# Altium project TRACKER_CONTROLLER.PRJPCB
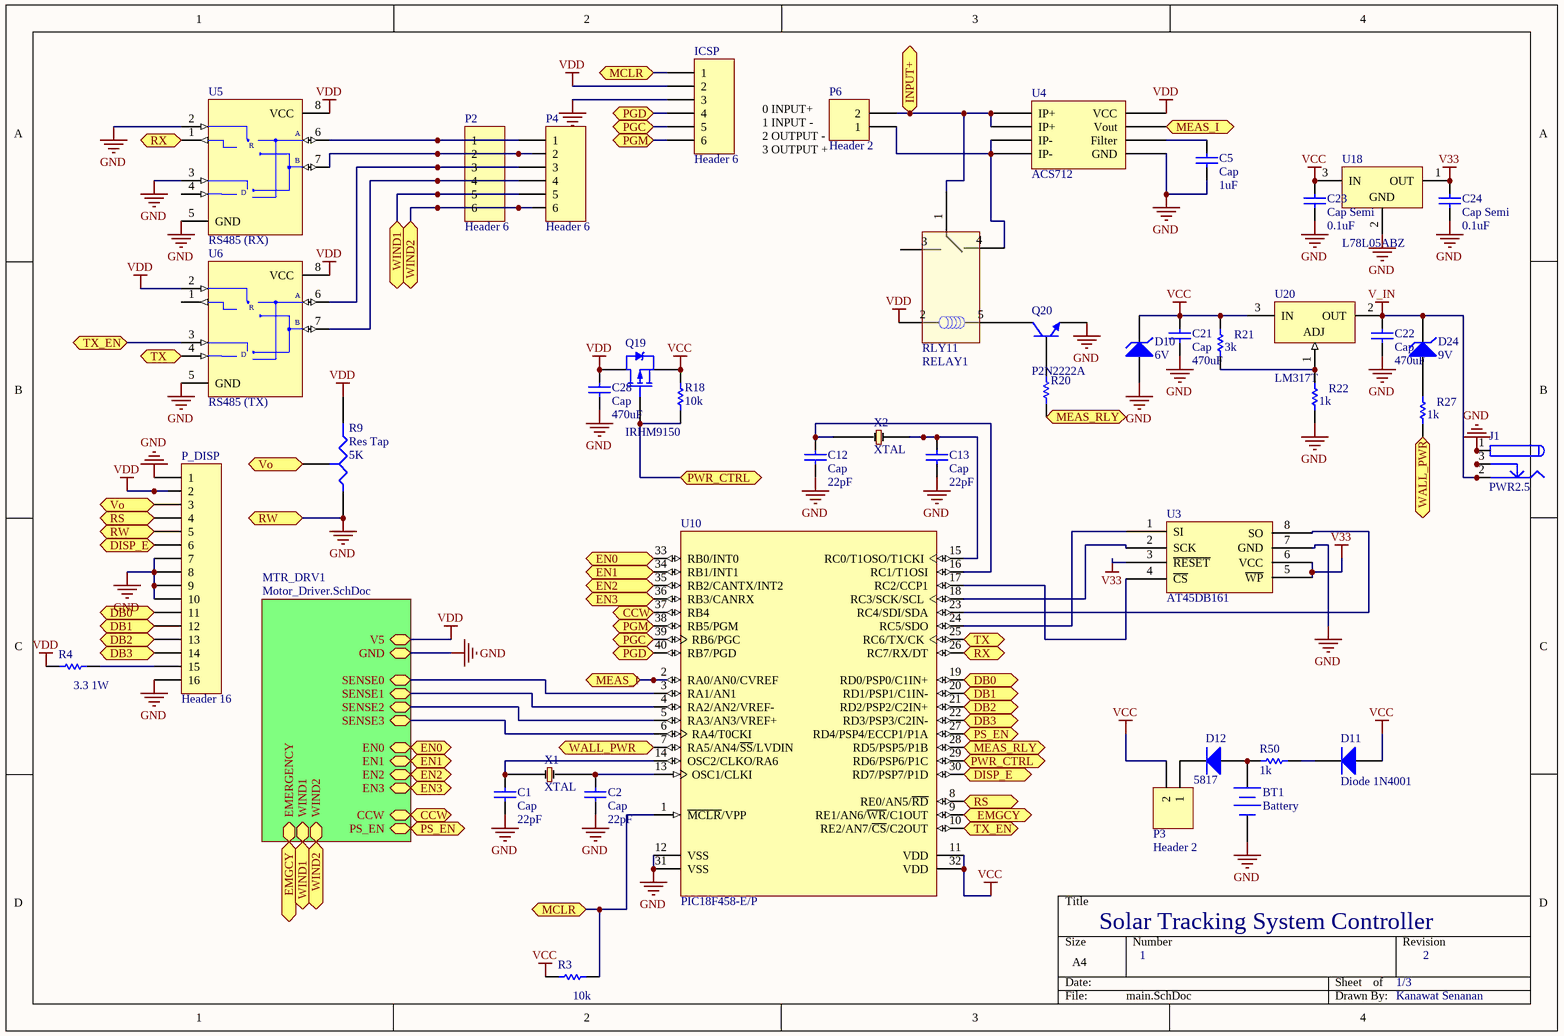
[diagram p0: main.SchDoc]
6 sheets, 202 parts. Net scope: hierarchical (ports join the sheet entries above them; power ports are global).
Board file: main_board.PcbDoc
Sheets:
  main.SchDoc
    MTR_DRV1 = Motor_Driver.SchDoc
      Sensor frontend = sensor_front.SchDoc
  Comm_interface.SchDoc
  current_logger.SchDoc
  main2.SchDoc
    MTR_DRV1 = Motor_Driver.SchDoc
      Sensor frontend = sensor_front.SchDoc

## Sheet main.SchDoc
size A4; PageSetup: Record=PageOptions|CenterHorizontal=True|CenterVertical=True|PrintScale=0.97|XCorrection=1.00|YCorrection=1.00|PrintKind=0|BorderSize=5000000|LeftOffset=0|BottomOffset=0|Orientation=2|PaperLength=1000|PaperWidth=1000|Scale=100|PaperSource=7|PrintQuality=-4|MediaType=1|DitherType=10|PaperKind=A4|PrintScaleMode=1

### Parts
(Parts that share a designator on the sheet are numbered #1, #2 ... from top to bottom, then left to right.)
BT1#1  Battery  [batt]
C1#1  Cap  value 22pF  [VP32-3.2]
C2#1  Cap  value 22pF  [VP32-3.2]
C5#1  Cap  value 1uF  [VP32-3.2]
C12#1  Cap  value 22pF  [VP32-3.2]
C13#1  Cap  value 22pF  [VP32-3.2]
C21#1  Cap  value 470uF  [Capacitor470u25v]
C22  Cap  value 470uF  [Capacitor470u25v]
C23#1  Cap Semi  value 0.1uF  [C1206]
C24#1  Cap Semi  value 0.1uF  [C1206]
C28#1  Cap  value 470uF  [Capacitor470u25v]
D10#1  6V  [DIODE-0.4]
D11#1  Diode 1N4001  [DO-41]
D12#1  5817  [DO-41]
D24  9V  [DIODE-0.4]
ICSP#1  Header 6  [HDR1X6]
J1  PWR2.5  [KLD-0202]
P2#1  Header 6  [PHONE_6]
P3#1  Header 2  [HDR1X2]
P4#1  Header 6  [PHONE_6]
P6#1  Header 2  [BLOCK_X2_762mm]
P_DISP#1  Header 16  [HDR1X16]
Q19#1  IRHM9150  [SSOT-3 - duplicate]
Q20  P2N2222A  [29-04]
R3#1  value 10k  [AXIAL-0.4]  (hidden comment: Res1)
R4#1  value 3.3 1W  [AXIAL-0.7]  (hidden comment: Res1)
R9#1  Res Tap  value 5K  [RPOT]
R18#1  value 10k  [AXIAL-0.4]  (hidden comment: Res1)
R20  Res1  [AXIAL-0.4]  (value not drawn)
R21  value 3k  [AXIAL-0.4]  (hidden comment: Res1)
R22  value 1k  [AXIAL-0.4]  (hidden comment: Res1)
R27  value 1k  [AXIAL-0.4]  (hidden comment: Res1)
R50#1  value 1k  [AXIAL-0.4]  (hidden comment: Res1)
RLY11  RELAY1  [SPDT]
U3#1  AT45DB161  [SOP8]
U4#1  ACS712  [751-05_N]
U5#1  RS485 (RX)  [PA8]
U6#1  RS485 (TX)  [PA8]
U10  PIC18F458-E/P  [PDIP600-40]
U18#1  L78L05ABZ  [TO92]
U20  LM317T  [221A-06]
X1#1  XTAL  [XTAL]
X2#1  XTAL  [XTAL]

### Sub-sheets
MTR_DRV1 = Motor_Driver.SchDoc: GND, SENSE0, SENSE1, SENSE2, SENSE3, EN0, EN1, EN2, EN3, CCW, V5, PS_EN, EMERGENCY, WIND1, WIND2

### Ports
CCW, DB0, DB1, DB2, DB3, DISP_E, EMGCY, EN0, EN1, EN2, EN3, INPUT+, MCLR, MEAS_I, MEAS_RLY, PGC, PGD, PGM, PS_EN, PWR_CTRL, RS, RW, RX, TX, TX_EN, Vo, WALL_PWR, WIND1, WIND2

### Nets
GND: BT1#1.2(-) C1#1.1 C2#1.1 C5#1.1 C12#1.1 C13#1.1 C21#1.2 C22.2 C23#1.1 C24#1.1 C28#1.2 D10#1.1(A) ICSP#1.3 J1.1 J1.1A J1.1B P_DISP#1.1 P_DISP#1.5 P_DISP#1.7 P_DISP#1.8 P_DISP#1.9 P_DISP#1.10 P_DISP#1.16 Q20.3(E) R9#1.1(A) R22.2 U3#1.7(GND) U4#1.5(GND) U5#1.2(~{RE}) U5#1.3(DE) U5#1.5(GND) U6#1.5(GND) U10.12(VSS) U10.31(VSS) U18#1.2(GND) ; port RW, sheet MTR_DRV1/GND
V33: C24#1.2 U3#1.3(~{RESET}) U3#1.5(~{WP}) U3#1.6(VCC) U18#1.1(OUT)
V_IN: C22.1 D24.2(K) J1.2 J1.2A J1.2B U20.2(OUT)
VCC: C21#1.1 C23#1.2 D10#1.2(K) D11#1.1(A) P3#1.2 Q19#1.2(S) R3#1.2 R18#1.1 R21.1 U10.11(VDD) U10.32(VDD) U18#1.3(IN) U20.3(IN)
VDD: C28#1.1 ICSP#1.2 P_DISP#1.2 Q19#1.1(D) R4#1.2 R9#1.2(B) RLY11.2 U4#1.8(VCC) U5#1.8(VCC) U6#1.2(~{RE}) U6#1.8(VCC) ; sheet MTR_DRV1/V5  [project net V5]
NetBT1#1_1: BT1#1.1(+) D12#1.1(A) R50#1.1
NetC1#1_2: C1#1.2 U10.14(OSC2/CLKO/RA6) X1#1.1
NetC2#1_2: C2#1.2 U10.13(OSC1/CLKI) X1#1.0
NetC5#1_2: C5#1.2 U4#1.6(Filter)
NetC12#1_2: C12#1.2 U10.16(RC1/T1OSI) X2#1.0
NetC13#1_2: C13#1.2 U10.15(RC0/T1OSO/T1CKI) X2#1.1
NetD1_1: P2#1.6 P4#1.6 ; port WIND2, sheet MTR_DRV1/WIND2
NetD1_2: P2#1.5 P4#1.5 ; port WIND1, sheet MTR_DRV1/WIND1
NetD11#1_2: D11#1.2(K) R50#1.2
NetD12#1_2: D12#1.2(K) P3#1.1
NetD24_1: D24.1(A) R27.1
NetICSP#1_1: ICSP#1.1 R3#1.1 U10.1(~{MCLR}/VPP) ; port MCLR
NetICSP#1_4: ICSP#1.4 U10.40(RB7/PGD) ; port PGD
NetICSP#1_5: ICSP#1.5 U10.39(RB6/PGC) ; port PGC
NetICSP#1_6: ICSP#1.6 U10.38(RB5/PGM) ; port PGM
NetJ1_3: J1.3 J1.3A J1.3B
NetP2#1_1: P2#1.1 P4#1.1 U5#1.6(A)
NetP2#1_2: P2#1.2 P4#1.2 U5#1.7(B)
NetP2#1_3: P2#1.3 P4#1.3 U6#1.6(A)
NetP2#1_4: P2#1.4 P4#1.4 U6#1.7(B)
NetP6#1_1: P6#1.1 RLY11.4 U4#1.3(IP-) U4#1.4(IP-)
NetP6#1_2: P6#1.2 RLY11.1 U4#1.1(IP+) U4#1.2(IP+) ; port INPUT+
NetP_DISP#1_3: P_DISP#1.3 R9#1.3(TAP) ; port Vo
NetP_DISP#1_4: P_DISP#1.4 U10.8(RE0/AN5/~{RD}) ; port RS
NetP_DISP#1_6: P_DISP#1.6 U10.30(RD7/PSP7/P1D) ; port DISP_E
NetP_DISP#1_11: P_DISP#1.11 U10.19(RD0/PSP0/C1IN+) ; port DB0
NetP_DISP#1_12: P_DISP#1.12 U10.20(RD1/PSP1/C1IN-) ; port DB1
NetP_DISP#1_13: P_DISP#1.13 U10.21(RD2/PSP2/C2IN+) ; port DB2
NetP_DISP#1_14: P_DISP#1.14 U10.22(RD3/PSP3/C2IN-) ; port DB3
NetP_DISP#1_15: P_DISP#1.15 R4#1.1
NetQ19#1_3: Q19#1.3(G) R18#1.2 U10.29(RD6/PSP6/P1C) ; port PWR_CTRL
NetQ20_1: Q20.1(C) RLY11.5
NetQ20_2: Q20.2(B) R20.1
NetR2_2: U10.9(RE1/AN6/~{WR}/C1OUT) ; port EMGCY, sheet MTR_DRV1/EMERGENCY
NetR20_2: R20.2 U10.28(RD5/PSP5/P1B) ; port MEAS_RLY
NetR21_2: R21.2 R22.1 U20.1(ADJ)
NetR27_2: R27.2 U10.7(RA5/AN4/~{SS}/LVDIN) ; port WALL_PWR
NetR103_2: U10.37(RB4) ; port CCW, sheet MTR_DRV1/CCW
NetU3#1_1: U3#1.1(SI) U10.24(RC5/SDO)
NetU3#1_2: U3#1.2(SCK) U10.18(RC3/SCK/SCL)
NetU3#1_4: U3#1.4(~{CS}) U10.17(RC2/CCP1)
NetU3#1_8: U3#1.8(SO) U10.23(RC4/SDI/SDA)
NetU4#1_7: U4#1.7(Vout) U10.2(RA0/AN0/CVREF) ; port MEAS_I
NetU5#1_1: U5#1.1(RO) U10.26(RC7/RX/DT) ; port RX
NetU6#1_3: U6#1.3(DE) U10.10(RE2/AN7/~{CS}/C2OUT) ; port TX_EN
NetU6#1_4: U6#1.4(DI) U10.25(RC6/TX/CK) ; port TX
NetU7_1: U10.33(RB0/INT0) ; port EN0, sheet MTR_DRV1/EN0
NetU7_3: U10.34(RB1/INT1) ; port EN1, sheet MTR_DRV1/EN1
NetU7_5: U10.35(RB2/CANTX/INT2) ; port EN2, sheet MTR_DRV1/EN2
NetU7_7: U10.36(RB3/CANRX) ; port EN3, sheet MTR_DRV1/EN3
NetU8_2: U10.3(RA1/AN1) ; sheet MTR_DRV1/SENSE0
NetU8_4: U10.4(RA2/AN2/VREF-) ; sheet MTR_DRV1/SENSE1
NetU8_6: U10.5(RA3/AN3/VREF+) ; sheet MTR_DRV1/SENSE2
NetU8_8: U10.6(RA4/T0CKI) ; sheet MTR_DRV1/SENSE3
NetU10_27: U10.27(RD4/PSP4/ECCP1/P1A) ; port PS_EN, sheet MTR_DRV1/PS_EN

Not connected (* = marked no-connect by the designer): RLY11 3; U5#1 4(DI); U6#1 1(RO)

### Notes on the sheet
- (near P6#1) 0 INPUT+
  1 INPUT -
  2 OUTPUT -
  3 OUTPUT +
- Solar Tracking System Controller
- 1
- 1/3
- 2
- Kanawat Senanan

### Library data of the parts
BT1#1 = Battery: Multicell Battery
C1#1 C2#1 C5#1 C12#1 C13#1 C21#1 C22 C28#1 = Cap: Capacitor
C23#1 C24#1 = Cap Semi: Capacitor (Semiconductor SIM Model)
D10#1 D24 = D Zener: Zener Diode
D11#1 D12#1 = Diode 1N4001: 1 Amp General Purpose Rectifier
ICSP#1 P2#1 P4#1 = Header 6: Header, 6-Pin
J1 = PWR2.5: Low Voltage Power Supply Connector
P3#1 P6#1 = Header 2: Header, 2-Pin
P_DISP#1 = Header 16: Header, 16-Pin
Q19#1 = IRHM9150: Radiation Hardened HEXFET Power MOSFET
Q20 = P2N2222A: Amplifier Transistor NPN Silicon
R3#1 R4#1 R18#1 R21 R22 R27 R50#1 = Res1: Resistor
R9#1 = Res Tap: Tapped Resistor; pin to pad: 2>3 3>2; Sim Note: Enter the Resistance value and the set point into parameter fields.; Set Position: 0.5
R20 = Res1: Resistor; Value: 2k
U5#1 U6#1 = MAX485EPA: Low-Power, Slew-Rate-Limited RS-485/RS-422 Transceiver
U10 = PIC18F458-E/P: High Performance, Enhanced FLASH Microcontroller with CAN, 32K FLASH, 40-Pin PDIP, Standard Volt Range, Extended Temperature
U18#1 = L78L05ABZ: Positive Voltage Regulator
U20 = LM317T: Three-Terminal Adjustable Output Positive Voltage Regulator; Note: Heatsink surface connected to Pin 2

## Sheet Motor_Driver.SchDoc
size A4; PageSetup: Record=PageOptions|CenterHorizontal=True|CenterVertical=True|PrintScale=0.97|XCorrection=1.00|YCorrection=1.00|PrintKind=0|BorderSize=5000000|LeftOffset=0|BottomOffset=0|Orientation=2|PaperLength=1000|PaperWidth=1000|Scale=100|PaperSource=7|PrintQuality=-4|MediaType=1|DitherType=10|PaperKind=A4|PrintScaleMode=1
Used 2 times, as channels MTR_DRV1, MTR_DRV1. Parts and nets are listed once, with the designators drawn on the sheet.
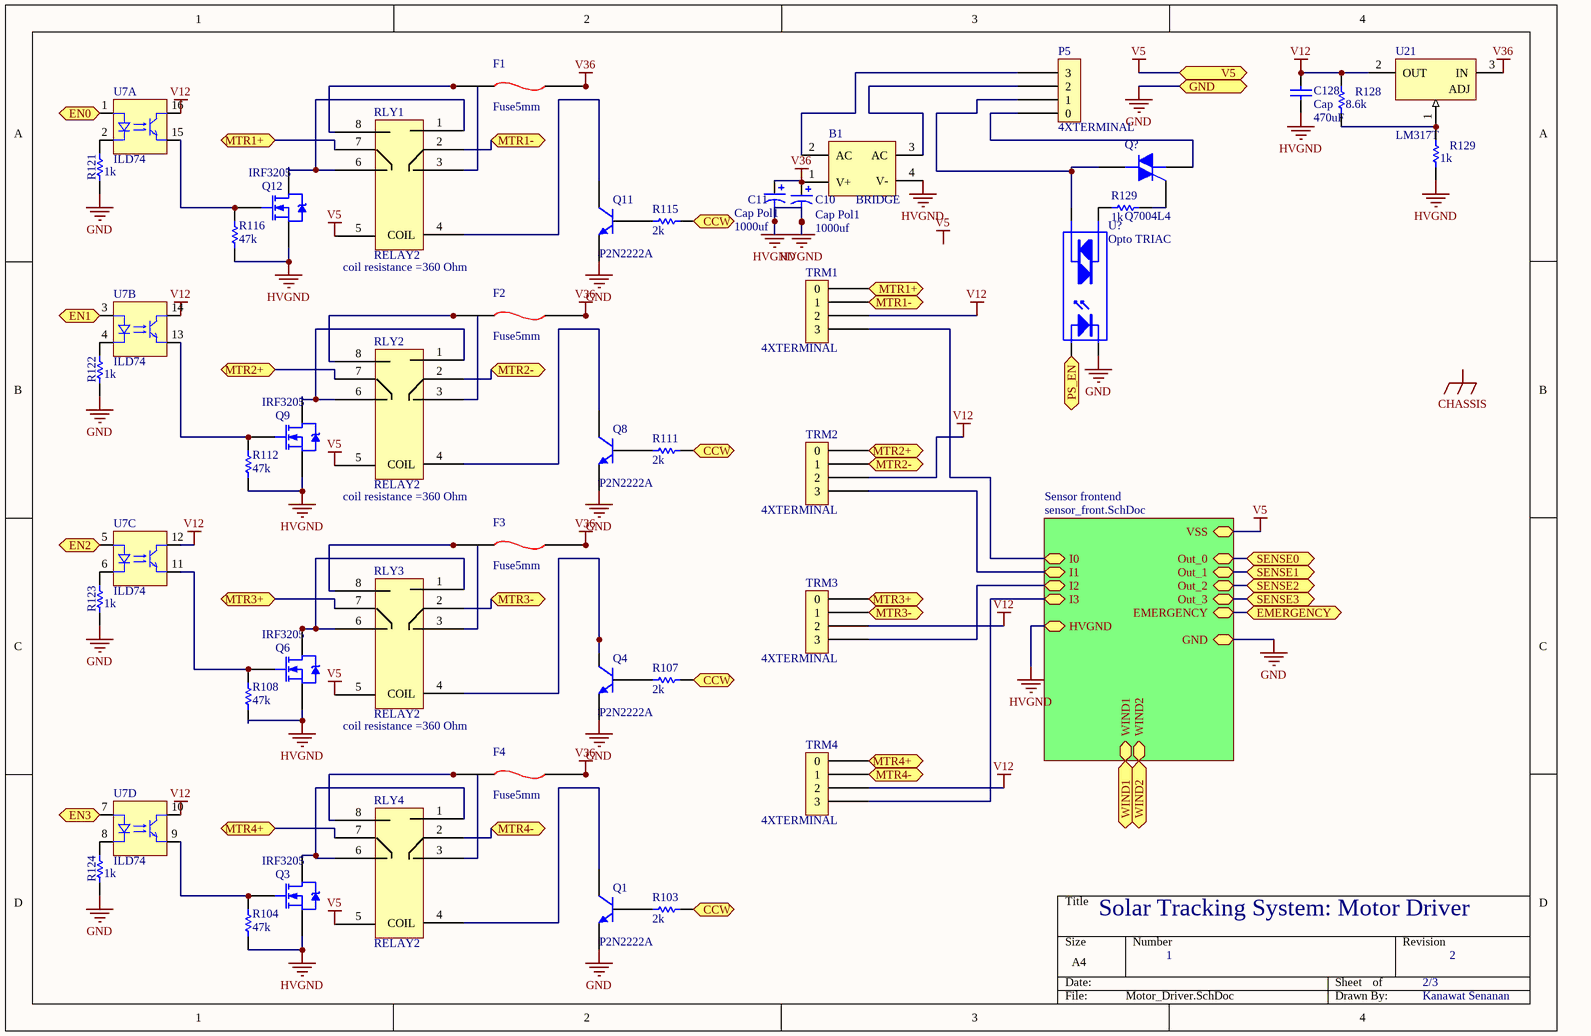
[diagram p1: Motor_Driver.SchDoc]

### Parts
(Parts that share a designator on the sheet are numbered #1, #2 ... from top to bottom, then left to right.)
B1  BRIDGE  [BRIDGE]
C10  Cap Pol1  value 1000uf  [Capacitor2200u50v]
C11  Cap Pol1  value 1000uf  [Capacitor2200u50v]
C128  Cap  value 470uF  [Capacitor470u25v]
F1  Fuse5mm  [Fuse5mm]
F2  Fuse5mm  [Fuse5mm]
F3  Fuse5mm  [Fuse5mm]
F4  Fuse5mm  [Fuse5mm]
P5  4XTERMINAL  [BLK_TERMX4]
Q1  P2N2222A  [29-04]
Q3  IRF3205  [TO-220AB]
Q4  P2N2222A  [29-04]
Q6  IRF3205  [TO-220AB]
Q8  P2N2222A  [29-04]
Q9  IRF3205  [TO-220AB]
Q11  P2N2222A  [29-04]
Q12  IRF3205  [TO-220AB]
Q?  Q7004L4  [TO-220AB]
R103  value 2k  [AXIAL-0.4]  (hidden comment: Res1)
R104  value 47k  [AXIAL-0.4]  (hidden comment: Res1)
R107  value 2k  [AXIAL-0.4]  (hidden comment: Res1)
R108  value 47k  [AXIAL-0.4]  (hidden comment: Res1)
R111  value 2k  [AXIAL-0.4]  (hidden comment: Res1)
R112  value 47k  [AXIAL-0.4]  (hidden comment: Res1)
R115  value 2k  [AXIAL-0.4]  (hidden comment: Res1)
R116  value 47k  [AXIAL-0.4]  (hidden comment: Res1)
R121  value 1k  [AXIAL-0.4]  (hidden comment: Res1)
R122  value 1k  [AXIAL-0.4]  (hidden comment: Res1)
R123  value 1k  [AXIAL-0.4]  (hidden comment: Res1)
R124  value 1k  [AXIAL-0.4]  (hidden comment: Res1)
R128  value 8.6k  [AXIAL-0.4]  (hidden comment: Res1)
R129#1  value 1k  [AXIAL-0.4]  (hidden comment: Res1)
R129#2  value 1k  [AXIAL-0.4]  (hidden comment: Res1)
RLY1  RELAY2  [DPDT_Relay]
RLY2  RELAY2  [DPDT_Relay]
RLY3  RELAY2  [DPDT_Relay]
RLY4  RELAY2  [DPDT_Relay]
TRM1  4XTERMINAL  [BLK_TERMX4]
TRM2  4XTERMINAL  [BLK_TERMX4]
TRM3  4XTERMINAL  [BLK_TERMX4]
TRM4  4XTERMINAL  [BLK_TERMX4]
U7  ILD74  [J016D]  (parts A,B,C,D of 4)
U21  LM317T  [221A-06]
U?  Opto TRIAC  [SIP-P4/A7.5]

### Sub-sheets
Sensor frontend = sensor_front.SchDoc: I0, I1, I2, I3, Out_0, Out_1, Out_2, Out_3, VSS, GND, HVGND, EMERGENCY, WIND1, WIND2

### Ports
CCW, EMERGENCY, EN0, EN1, EN2, EN3, GND, MTR1+, MTR1-, MTR2+, MTR2-, MTR3+, MTR3-, MTR4+, MTR4-, PS_EN, SENSE0, SENSE1, SENSE2, SENSE3, V5, WIND1, WIND2

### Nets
GND: Q1.3(E) Q4.3(E) Q8.3(E) Q11.3(E) R121.1 R122.1 R123.1 R124.1 U?.2(K) ; port GND, sheet Sensor frontend/GND
HVGND: B1.4(V-) C10.2 C11.2 C128.2 Q3.3(S) Q6.3(S) Q9.3(S) Q12.3(S) R104.1 R108.1 R112.1 R116.1 R129#1.2 ; sheet Sensor frontend/HVGND
V5: RLY1.5 RLY2.5 RLY3.5 RLY4.5 ; port V5, sheet Sensor frontend/VSS
V12: C128.1 R128.1 TRM1.2 TRM2.2 TRM3.2 TRM4.2 U7.10(C) U7.12(C) U7.14(C) U7.16(C) U21.2(OUT)
V36: B1.1(V+) C10.1 C11.1 F1.3 F1.4 F2.3 F2.4 F3.3 F3.4 F4.3 F4.4 U21.3(IN)
CCW: R103.2 R107.2 R111.2 R115.2 ; port CCW
EMERGENCY: port EMERGENCY, sheet Sensor frontend/EMERGENCY
EN0: U7.1(A) ; port EN0
EN1: U7.3(A) ; port EN1
EN2: U7.5(A) ; port EN2
EN3: U7.7(A) ; port EN3
MTR1+: RLY1.7 TRM1.0 ; port MTR1+
MTR1-: RLY1.2 TRM1.1 ; port MTR1-
MTR2+: RLY2.7 TRM2.0 ; port MTR2+
MTR2-: RLY2.2 TRM2.1 ; port MTR2-
MTR3+: RLY3.7 TRM3.0 ; port MTR3+
MTR3-: RLY3.2 TRM3.1 ; port MTR3-
MTR4+: RLY4.7 TRM4.0 ; port MTR4+
MTR4-: RLY4.2 TRM4.1 ; port MTR4-
PS_EN: U?.1(A) ; port PS_EN
SENSE0: port SENSE0, sheet Sensor frontend/Out_0
SENSE1: port SENSE1, sheet Sensor frontend/Out_1
SENSE2: port SENSE2, sheet Sensor frontend/Out_2
SENSE3: port SENSE3, sheet Sensor frontend/Out_3
WIND1: port WIND1, sheet Sensor frontend/WIND1
WIND2: port WIND2, sheet Sensor frontend/WIND2
NetB1_2: B1.2(AC) P5.3
NetB1_3: B1.3(AC) P5.2
NetF1_1: F1.1 F1.2 RLY1.3 RLY1.8
NetF2_1: F2.1 F2.2 RLY2.3 RLY2.8
NetF3_1: F3.1 F3.2 RLY3.3 RLY3.8
NetF4_1: F4.1 F4.2 RLY4.3 RLY4.8
NetP5_0: P5.0 Q?.1(M1)
NetP5_1: P5.1 Q?.2(M2) U?.3(A/K)
NetQ1_1: Q1.1(C) RLY4.4(COIL)
NetQ1_2: Q1.2(B) R103.1
NetQ3_1: Q3.1(G) R104.2 U7.9(E)
NetQ3_2: Q3.2(D) RLY4.1(NO) RLY4.6
NetQ4_1: Q4.1(C) RLY3.4(COIL)
NetQ4_2: Q4.2(B) R107.1
NetQ6_1: Q6.1(G) R108.2 U7.11(E)
NetQ6_2: Q6.2(D) RLY3.1(NO) RLY3.6
NetQ8_1: Q8.1(C) RLY2.4(COIL)
NetQ8_2: Q8.2(B) R111.1
NetQ9_1: Q9.1(G) R112.2 U7.13(E)
NetQ9_2: Q9.2(D) RLY2.1(NO) RLY2.6
NetQ11_1: Q11.1(C) RLY1.4(COIL)
NetQ11_2: Q11.2(B) R115.1
NetQ12_1: Q12.1(G) R116.2 U7.15(E)
NetQ12_2: Q12.2(D) RLY1.1(NO) RLY1.6
NetQ?_3: Q?.3(G) R129#2.2
NetR121_2: R121.2 U7.2(K)
NetR122_2: R122.2 U7.4(K)
NetR123_2: R123.2 U7.6(K)
NetR124_2: R124.2 U7.8(K)
NetR128_2: R128.2 R129#1.1 U21.1(ADJ)
NetR129#2_1: R129#2.1 U?.4(A/K)
NetTRM1_3: TRM1.3 ; sheet Sensor frontend/I0
NetTRM2_3: TRM2.3 ; sheet Sensor frontend/I1
NetTRM3_3: TRM3.3 ; sheet Sensor frontend/I2
NetTRM4_3: TRM4.3 ; sheet Sensor frontend/I3

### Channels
MTR_DRV1: designators B1=B1 C10=C10 C11=C11 C128=C128 F1=F1 F2=F2 F3=F3 F4=F4 P5=P5_MTR_DRV1#1 Q1=Q1 Q3=Q3 Q4=Q4 Q6=Q6 Q8=Q8 Q9=Q9 Q11=Q11 Q12=Q12 Q?=Q?_MTR_DRV1#1 R103=R103 R104=R104 R107=R107 R108=R108 R111=R111 R112=R112 R115=R115 R116=R116 R121=R121 R122=R122 R123=R123 R124=R124 R128=R128 R129=R129 R129=R129_MTR_DRV1#1 RLY1=RLY1_MTR_DRV1#1 RLY2=RLY2_MTR_DRV1#1 RLY3=RLY3 RLY4=RLY4 TRM1=TRM1 TRM2=TRM2 TRM3=TRM3 TRM4=TRM4 U7=U7 U21=U21 U?=U?_MTR_DRV1#1; ports CCW=NetR103_2 EMERGENCY=NetR2_2 EN0=NetU7_1 EN1=NetU7_3 EN2=NetU7_5 EN3=NetU7_7 GND=GND MTR1+=NetRLY1_MTR_DRV1#1_7 MTR1-=NetRLY1_MTR_DRV1#1_2 MTR2+=NetRLY2_MTR_DRV1#1_7 MTR2-=NetRLY2_MTR_DRV1#1_2 MTR3+=NetRLY3_7 MTR3-=NetRLY3_2 MTR4+=NetRLY4_7 MTR4-=NetRLY4_2 PS_EN=NetU10_27 SENSE0=NetU8_2 SENSE1=NetU8_4 SENSE2=NetU8_6 SENSE3=NetU8_8 V5=V5 WIND1=NetD1_2 WIND2=NetD1_1
MTR_DRV1: designators B1=B1_MTR_DRV1 C10=C10_MTR_DRV1 C11=C11_MTR_DRV1 C128=C128_MTR_DRV1 F1=F1_MTR_DRV1 F2=F2_MTR_DRV1 F3=F3_MTR_DRV1 F4=F4_MTR_DRV1 P5=P5_MTR_DRV1#2 Q1=Q1_MTR_DRV1 Q3=Q3_MTR_DRV1 Q4=Q4_MTR_DRV1 Q6=Q6_MTR_DRV1 Q8=Q8_MTR_DRV1 Q9=Q9_MTR_DRV1 Q11=Q11_MTR_DRV1 Q12=Q12_MTR_DRV1 Q?=Q?_MTR_DRV1#2 R103=R103_MTR_DRV1 R104=R104_MTR_DRV1 R107=R107_MTR_DRV1 R108=R108_MTR_DRV1 R111=R111_MTR_DRV1 R112=R112_MTR_DRV1 R115=R115_MTR_DRV1 R116=R116_MTR_DRV1 R121=R121_MTR_DRV1 R122=R122_MTR_DRV1 R123=R123_MTR_DRV1 R124=R124_MTR_DRV1 R128=R128_MTR_DRV1 R129=R129_MTR_DRV1#2 R129=R129_MTR_DRV1#3 RLY1=RLY1_MTR_DRV1#2 RLY2=RLY2_MTR_DRV1#2 RLY3=RLY3_MTR_DRV1 RLY4=RLY4_MTR_DRV1 TRM1=TRM1_MTR_DRV1 TRM2=TRM2_MTR_DRV1 TRM3=TRM3_MTR_DRV1 TRM4=TRM4_MTR_DRV1 U7=U7_MTR_DRV1 U21=U21_MTR_DRV1 U?=U?_MTR_DRV1#2; ports CCW=NetR103_MTR_DRV1_2 EMERGENCY=NetR2_MTR_DRV1_Sensor_frontend_2 EN0=NetU7_MTR_DRV1_1 EN1=NetU7_MTR_DRV1_3 EN2=NetU7_MTR_DRV1_5 EN3=NetU7_MTR_DRV1_7 GND=GND MTR1+=NetRLY1_MTR_DRV1#2_7 MTR1-=NetRLY1_MTR_DRV1#2_2 MTR2+=NetRLY2_MTR_DRV1#2_7 MTR2-=NetRLY2_MTR_DRV1#2_2 MTR3+=NetRLY3_MTR_DRV1_7 MTR3-=NetRLY3_MTR_DRV1_2 MTR4+=NetRLY4_MTR_DRV1_7 MTR4-=NetRLY4_MTR_DRV1_2 PS_EN=NetU?_MTR_DRV1#2_1 SENSE0=NetU8_MTR_DRV1_Sensor_frontend_2 SENSE1=NetU8_MTR_DRV1_Sensor_frontend_4 SENSE2=NetU7_MTR_DRV1_1 SENSE3=NetU8_MTR_DRV1_Sensor_frontend_8 V5=V5 WIND1=NetD1_MTR_DRV1_Sensor_frontend_2 WIND2=NetD1_MTR_DRV1_Sensor_frontend_1

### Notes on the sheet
- coil resistance =360 Ohm
- Solar Tracking System: Motor Driver
- 1
- 2/3
- 2
- Kanawat Senanan
- Labels drawn without touching a wire or pin: CHASSIS, V5

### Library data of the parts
C10 C11 = Cap Pol1: Polarized Capacitor (Radial)
C128 = Cap: Capacitor
Q1 Q4 Q8 Q11 = P2N2222A: Amplifier Transistor NPN Silicon
Q3 Q6 Q9 Q12 = IRF3205: HEXFET Power MOSFET; Note: Pin 2 is electrically connected to pin 4.
Q? = Q7004L4: Triac (4.0 Amps); Note: Tab is electrically isolated
R103 R104 R107 R108 R111 R112 R115 R116 R121-R124 R128 R129#1 R129#2 = Res1: Resistor
U7 = ILD74: Optocoupler, Phototransistor Output, Dual Channel, TTL Compatible, Pb-free; Note: Coupling Capacitance, 0.5 pF; Note: Transfer Ratio, 35 % Typical
U21 = LM317T: as U20 on sheet main
U? = Opto TRIAC: Opto-Triac

## Sheet sensor_front.SchDoc
size A4; PageSetup: Record=PageOptions|CenterHorizontal=True|CenterVertical=True|PrintScale=0.97|XCorrection=1.00|YCorrection=1.00|PrintKind=0|BorderSize=5000000|LeftOffset=0|BottomOffset=0|Orientation=2|PaperLength=1000|PaperWidth=1000|Scale=100|PaperSource=7|PrintQuality=-4|MediaType=1|DitherType=10|PaperKind=A4|PrintScaleMode=1
Used 2 times, as channels MTR_DRV1/Sensor frontend, MTR_DRV1/Sensor frontend. Parts and nets are listed once, with the designators drawn on the sheet.
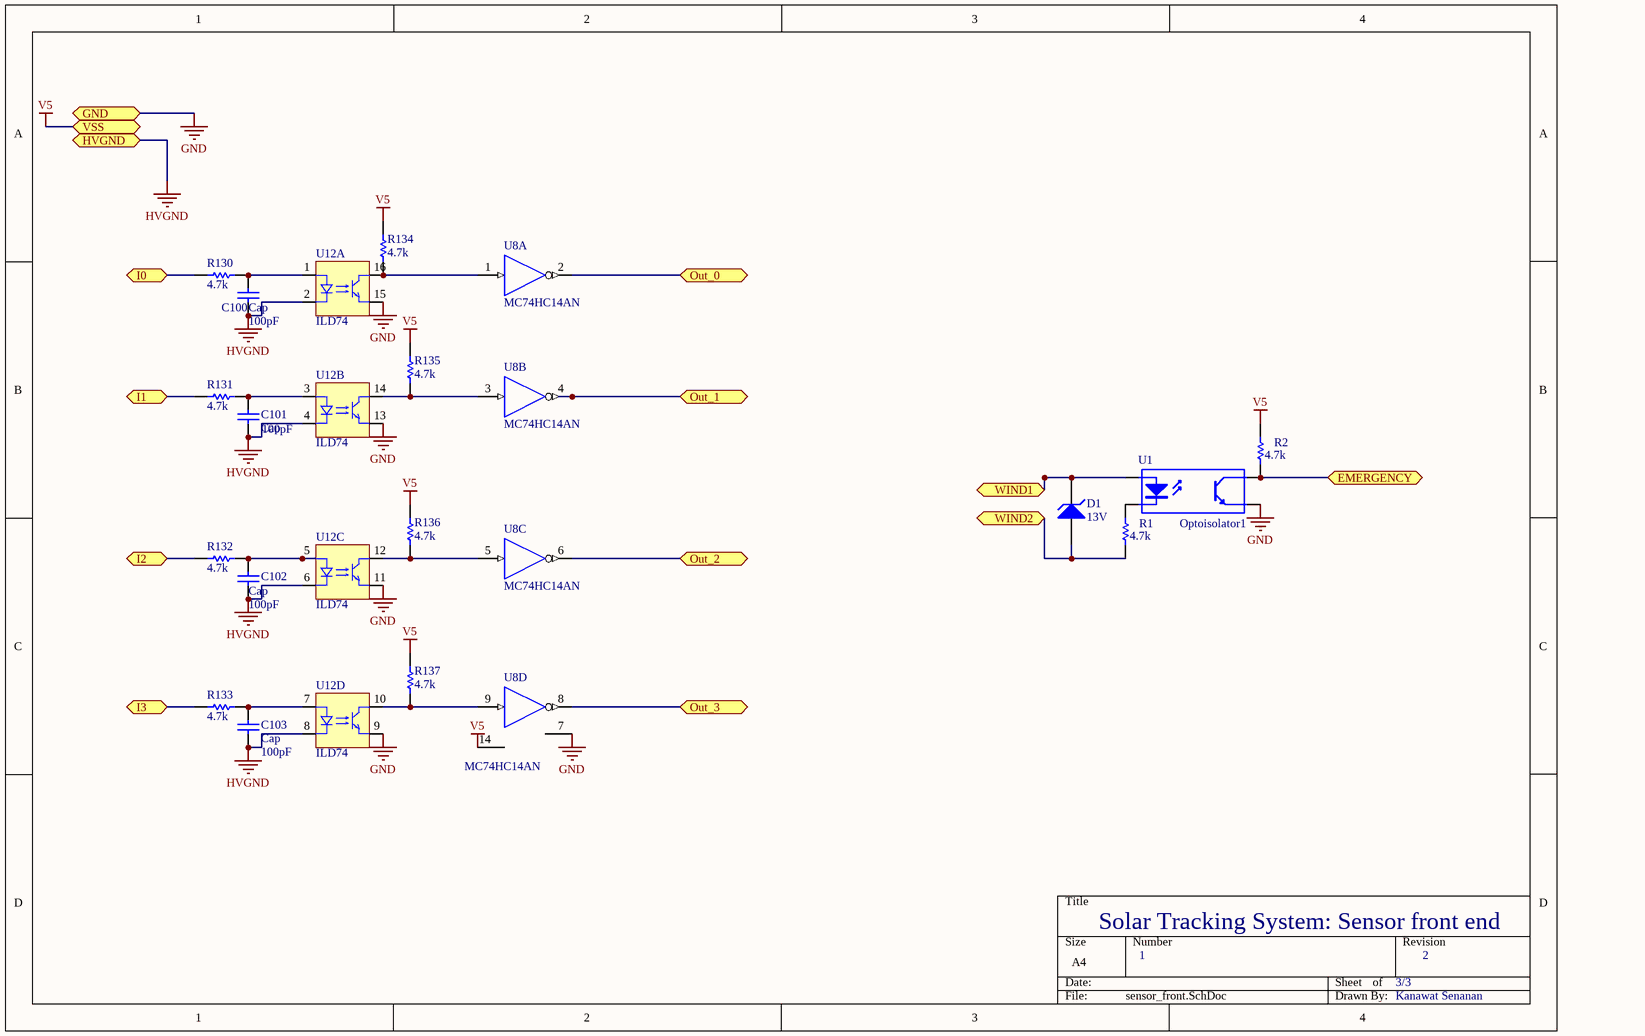
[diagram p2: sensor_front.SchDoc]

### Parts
C100  Cap  value 100pF  [VP45-3.2]
C101  Cap  value 100pF  [VP45-3.2]
C102  Cap  value 100pF  [VP45-3.2]
C103  Cap  value 100pF  [VP45-3.2]
D1  13V  [DIODE-0.4]
R1  value 4.7k  [AXIAL-0.4]  (hidden comment: Res1)
R2  value 4.7k  [AXIAL-0.4]  (hidden comment: Res1)
R130  value 4.7k  [AXIAL-0.4]  (hidden comment: Res1)
R131  value 4.7k  [AXIAL-0.4]  (hidden comment: Res1)
R132  value 4.7k  [AXIAL-0.4]  (hidden comment: Res1)
R133  value 4.7k  [AXIAL-0.4]  (hidden comment: Res1)
R134  value 4.7k  [AXIAL-0.4]  (hidden comment: Res1)
R135  value 4.7k  [AXIAL-0.4]  (hidden comment: Res1)
R136  value 4.7k  [AXIAL-0.4]  (hidden comment: Res1)
R137  value 4.7k  [AXIAL-0.4]  (hidden comment: Res1)
U1  Optoisolator1  [DIP-4]
U8  MC74HC14AN  [646-06]  (parts A,B,C,D of 6)
U12  ILD74  [J016D]  (parts A,B,C,D of 4)

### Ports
EMERGENCY, GND, HVGND, I0, I1, I2, I3, Out_0, Out_1, Out_2, Out_3, VSS, WIND1, WIND2

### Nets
GND: U1.3(E) U8.7(GND) U12.9(E) U12.11(E) U12.13(E) U12.15(E) ; port GND
HVGND: C100.1 C101.1 C102.1 C103.1 U12.2(K) U12.4(K) U12.6(K) U12.8(K) ; port HVGND
V5: R2.1 R134.1 R135.1 R136.1 R137.1 U8.14(VDD) ; port VSS  [also labelled VDD]
EMERGENCY: R2.2 U1.4(C) ; port EMERGENCY
I0: R130.2 ; port I0
I1: R131.2 ; port I1
I2: R132.2 ; port I2
I3: R133.2 ; port I3
Out_0: U8.2(Y) ; port Out_0
Out_1: U8.4(Y) ; port Out_1
Out_2: U8.6(Y) ; port Out_2
Out_3: U8.8(Y) ; port Out_3
WIND1: D1.2(K) U1.1(A) ; port WIND1
WIND2: D1.1(A) R1.2 ; port WIND2
NetC100_2: C100.2 R130.1 U12.1(A)
NetC101_2: C101.2 R131.1 U12.3(A)
NetC102_2: C102.2 R132.1 U12.5(A)
NetC103_2: C103.2 R133.1 U12.7(A)
NetR1_1: R1.1 U1.2(K)
NetR134_2: R134.2 U8.1(A) U12.16(C)
NetR135_2: R135.2 U8.3(A) U12.14(C)
NetR136_2: R136.2 U8.5(A) U12.12(C)
NetR137_2: R137.2 U8.9(A) U12.10(C)

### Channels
MTR_DRV1/Sensor frontend: designators C100=C100_MTR_DRV1_Sensor_frontend#1 C101=C101_MTR_DRV1_Sensor_frontend#1 C102=C102_MTR_DRV1_Sensor_frontend#1 C103=C103_MTR_DRV1_Sensor_frontend#1 D1=D1 R1=R1 R2=R2 R130=R130_MTR_DRV1_Sensor_frontend#1 R131=R131_MTR_DRV1_Sensor_frontend#1 R132=R132_MTR_DRV1_Sensor_frontend#1 R133=R133_MTR_DRV1_Sensor_frontend#1 R134=R134 R135=R135_MTR_DRV1_Sensor_frontend#1 R136=R136 R137=R137 U1=U1 U8=U8 U12=U12; ports EMERGENCY=NetR2_2 GND=GND HVGND=HVGND I0=NetR130_MTR_DRV1_Sensor_frontend#1_2 I1=NetR131_MTR_DRV1_Sensor_frontend#1_2 I2=NetR132_MTR_DRV1_Sensor_frontend#1_2 I3=NetR133_MTR_DRV1_Sensor_frontend#1_2 Out_0=NetU8_2 Out_1=NetU8_4 Out_2=NetU8_6 Out_3=NetU8_8 VSS=V5 WIND1=NetD1_2 WIND2=NetD1_1
MTR_DRV1/Sensor frontend: designators C100=C100_MTR_DRV1_Sensor_frontend#2 C101=C101_MTR_DRV1_Sensor_frontend#2 C102=C102_MTR_DRV1_Sensor_frontend#2 C103=C103_MTR_DRV1_Sensor_frontend#2 D1=D1_MTR_DRV1_Sensor_frontend R1=R1_MTR_DRV1_Sensor_frontend R2=R2_MTR_DRV1_Sensor_frontend R130=R130_MTR_DRV1_Sensor_frontend#2 R131=R131_MTR_DRV1_Sensor_frontend#2 R132=R132_MTR_DRV1_Sensor_frontend#2 R133=R133_MTR_DRV1_Sensor_frontend#2 R134=R134_MTR_DRV1_Sensor_frontend R135=R135_MTR_DRV1_Sensor_frontend#2 R136=R136_MTR_DRV1_Sensor_frontend R137=R137_MTR_DRV1_Sensor_frontend U1=U1_MTR_DRV1_Sensor_frontend U8=U8_MTR_DRV1_Sensor_frontend U12=U12_MTR_DRV1_Sensor_frontend; ports EMERGENCY=NetR2_MTR_DRV1_Sensor_frontend_2 GND=GND HVGND=HVGND I0=NetR130_MTR_DRV1_Sensor_frontend#2_2 I1=NetR131_MTR_DRV1_Sensor_frontend#2_2 I2=NetR132_MTR_DRV1_Sensor_frontend#2_2 I3=NetR133_MTR_DRV1_Sensor_frontend#2_2 Out_0=NetU8_MTR_DRV1_Sensor_frontend_2 Out_1=NetU8_MTR_DRV1_Sensor_frontend_4 Out_2=NetU7_MTR_DRV1_1 Out_3=NetU8_MTR_DRV1_Sensor_frontend_8 VSS=V5 WIND1=NetD1_MTR_DRV1_Sensor_frontend_2 WIND2=NetD1_MTR_DRV1_Sensor_frontend_1

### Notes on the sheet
- Solar Tracking System: Sensor front end
- 1
- 3/3
- 2
- Kanawat Senanan

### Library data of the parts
C100-C103 = Cap: Capacitor
D1 = D Zener: Zener Diode
R1 R2 R130-R137 = Res1: Resistor
U1 = Optoisolator1: 4-Pin Phototransistor Optocoupler
U8 = MC74HC14AN: Hex Schmitt Trigger Inverter
U12 = ILD74: as U7 on sheet Motor_Driver

## Sheet Comm_interface.SchDoc
size A

## Sheet current_logger.SchDoc
size A
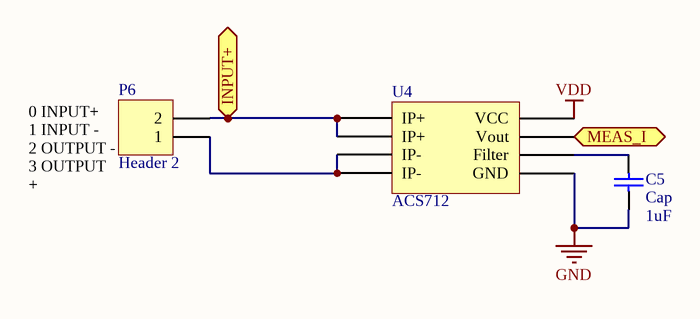
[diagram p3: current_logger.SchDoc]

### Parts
(Parts that share a designator on the sheet are numbered #1, #2 ... from top to bottom, then left to right.)
C5#2  Cap  value 1uF  [VP32-3.2]
P6#2  Header 2  [BLOCK_X2_762mm]
U4#2  ACS712  [751-05_N]

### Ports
INPUT+, MEAS_I

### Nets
GND: C5#2.1 U4#2.5(GND)
VDD: U4#2.8(VCC)  [project net V5]
NetC5#2_2: C5#2.2 U4#2.6(Filter)
NetP6#2_1: P6#2.1 U4#2.3(IP-) U4#2.4(IP-)
NetP6#2_2: P6#2.2 U4#2.1(IP+) U4#2.2(IP+) ; port INPUT+
NetU4#2_7: U4#2.7(Vout) ; port MEAS_I

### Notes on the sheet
- (near P6#2) 0 INPUT+
  1 INPUT -
  2 OUTPUT -
  3 OUTPUT +

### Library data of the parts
C5#2 = Cap: Capacitor
P6#2 = Header 2: Header, 2-Pin

## Sheet main2.SchDoc
size A4; PageSetup: Record=PageOptions|CenterHorizontal=True|CenterVertical=True|PrintScale=0.97|XCorrection=1.00|YCorrection=1.00|PrintKind=0|BorderSize=5000000|LeftOffset=0|BottomOffset=0|Orientation=2|PaperLength=1000|PaperWidth=1000|Scale=100|PaperSource=7|PrintQuality=-4|MediaType=1|DitherType=10|PaperKind=A4|PrintScaleMode=1
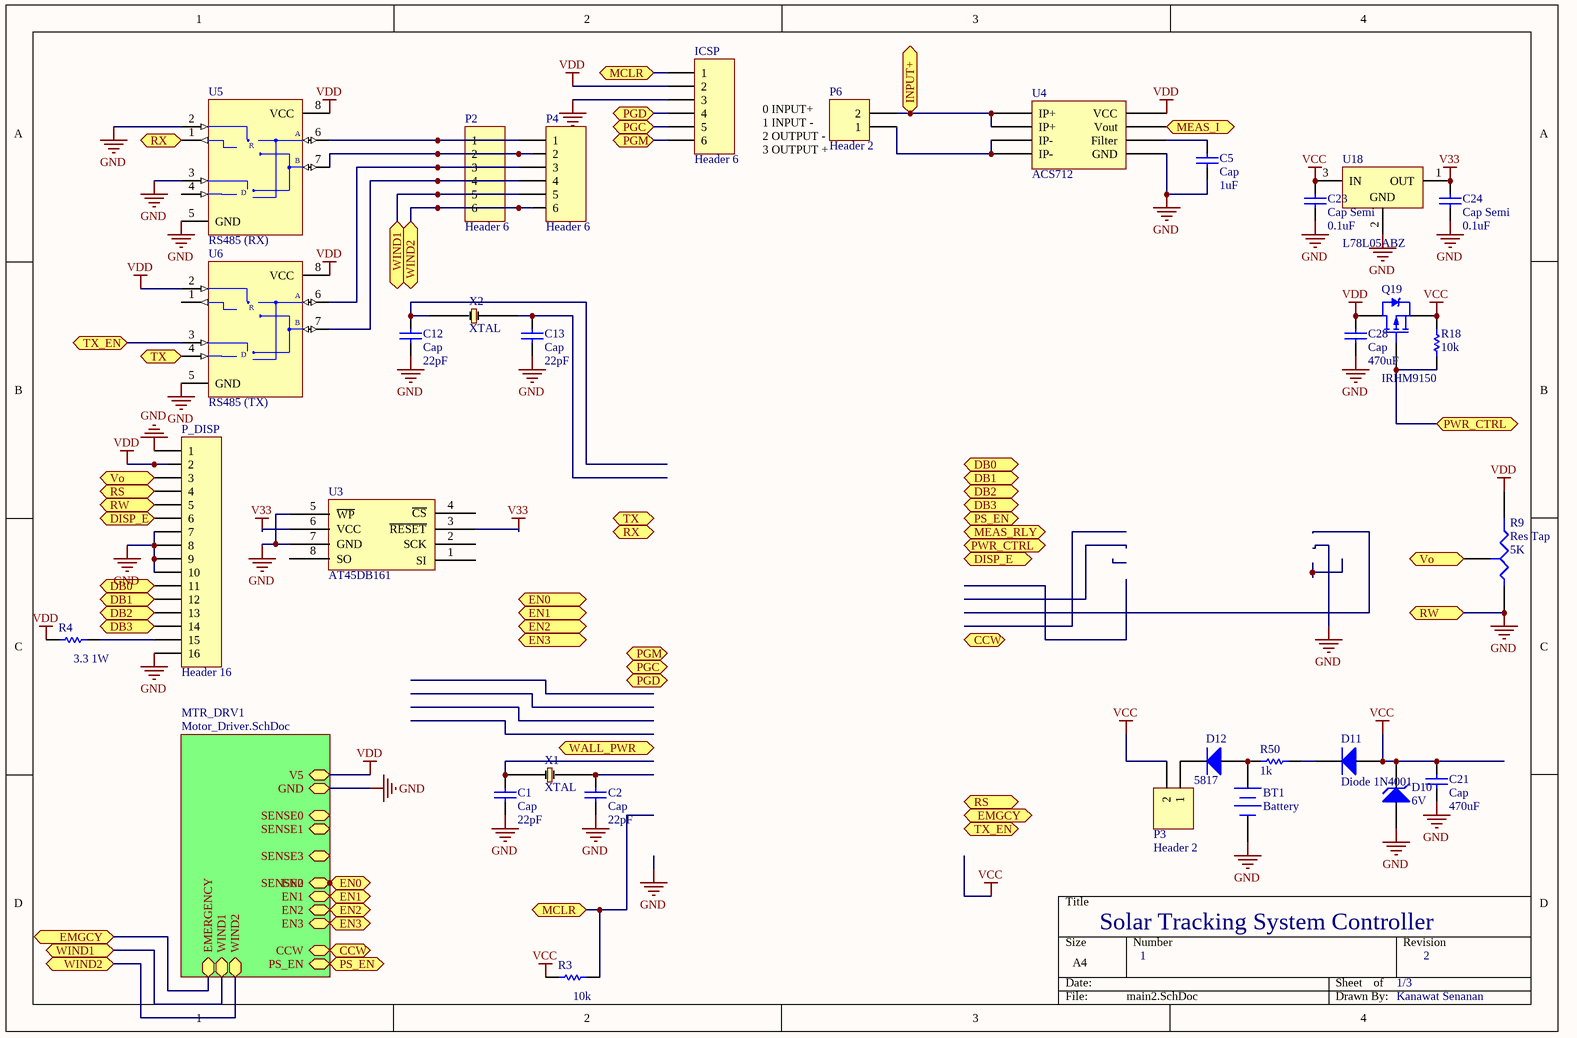
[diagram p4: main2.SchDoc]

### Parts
(Parts that share a designator on the sheet are numbered #1, #2 ... from top to bottom, then left to right.)
BT1#2  Battery  [batt]
C1#2  Cap  value 22pF  [VP32-3.2]
C2#2  Cap  value 22pF  [VP32-3.2]
C5#3  Cap  value 1uF  [VP32-3.2]
C12#2  Cap  value 22pF  [VP32-3.2]
C13#2  Cap  value 22pF  [VP32-3.2]
C21#2  Cap  value 470uF  [Capacitor470u25v]
C23#2  Cap Semi  value 0.1uF  [C1206]
C24#2  Cap Semi  value 0.1uF  [C1206]
C28#2  Cap  value 470uF  [Capacitor470u25v]
D10#2  6V  [DIODE-0.4]
D11#2  Diode 1N4001  [DO-41]
D12#2  5817  [DO-41]
ICSP#2  Header 6  [HDR1X6]
P2#2  Header 6  [PHONE_6]
P3#2  Header 2  [HDR1X2]
P4#2  Header 6  [PHONE_6]
P6#3  Header 2  [BLOCK_X2_762mm]
P_DISP#2  Header 16  [HDR1X16]
Q19#2  IRHM9150  [SSOT-3 - duplicate]
R3#2  value 10k  [AXIAL-0.4]  (hidden comment: Res1)
R4#2  value 3.3 1W  [AXIAL-0.7]  (hidden comment: Res1)
R9#2  Res Tap  value 5K  [RPOT]
R18#2  value 10k  [AXIAL-0.4]  (hidden comment: Res1)
R50#2  value 1k  [AXIAL-0.4]  (hidden comment: Res1)
U3#2  AT45DB161  [SOP8]
U4#3  ACS712  [751-05_N]
U5#2  RS485 (RX)  [PA8]
U6#2  RS485 (TX)  [PA8]
U18#2  L78L05ABZ  [TO92]
X1#2  XTAL  [XTAL]
X2#2  XTAL  [XTAL]

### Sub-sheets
MTR_DRV1 = Motor_Driver.SchDoc: GND, SENSE0, SENSE1, SENSE2, SENSE3, EN0, EN1, EN2, EN3, CCW, V5, PS_EN, EMERGENCY, WIND1, WIND2

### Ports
CCW, DB0, DB1, DB2, DB3, DISP_E, EMGCY, EN0, EN1, EN2, EN3, INPUT+, MCLR, MEAS_I, MEAS_RLY, PGC, PGD, PGM, PS_EN, PWR_CTRL, RS, RW, RX, TX, TX_EN, Vo, WALL_PWR, WIND1, WIND2

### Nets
GND: BT1#2.2(-) C1#2.1 C2#2.1 C5#3.1 C12#2.1 C13#2.1 C21#2.2 C23#2.1 C24#2.1 C28#2.2 D10#2.1(A) ICSP#2.3 P_DISP#2.1 P_DISP#2.5 P_DISP#2.7 P_DISP#2.8 P_DISP#2.9 P_DISP#2.10 P_DISP#2.16 R9#2.1(A) U3#2.5(~{WP}) U3#2.7(GND) U4#3.5(GND) U5#2.2(~{RE}) U5#2.3(DE) U5#2.5(GND) U6#2.5(GND) U18#2.2(GND) ; port RW, sheet MTR_DRV1/GND
V33: C24#2.2 U3#2.3(~{RESET}) U3#2.6(VCC) U18#2.1(OUT)
VCC: C21#2.1 C23#2.2 D10#2.2(K) D11#2.1(A) P3#2.2 Q19#2.2(S) R3#2.2 R18#2.1 U18#2.3(IN)
VDD: C28#2.1 ICSP#2.2 P_DISP#2.2 Q19#2.1(D) R4#2.2 R9#2.2(B) U4#3.8(VCC) U5#2.8(VCC) U6#2.2(~{RE}) U6#2.8(VCC) ; sheet MTR_DRV1/V5  [project net V5]
NetBT1#2_1: BT1#2.1(+) D12#2.1(A) R50#2.1
NetC1#2_2: C1#2.2 X1#2.1
NetC2#2_2: C2#2.2 X1#2.0
NetC5#3_2: C5#3.2 U4#3.6(Filter)
NetC12#2_2: C12#2.2 X2#2.0
NetC13#2_2: C13#2.2 X2#2.1
NetD1_MTR_DRV1_Sensor_frontend_1: P2#2.6 P4#2.6 ; port WIND2, sheet MTR_DRV1/WIND2
NetD1_MTR_DRV1_Sensor_frontend_2: P2#2.5 P4#2.5 ; port WIND1, sheet MTR_DRV1/WIND1
NetD11#2_2: D11#2.2(K) R50#2.2
NetD12#2_2: D12#2.2(K) P3#2.1
NetICSP#2_1: ICSP#2.1 R3#2.1 ; port MCLR
NetICSP#2_4: ICSP#2.4 ; port PGD
NetICSP#2_5: ICSP#2.5 ; port PGC
NetICSP#2_6: ICSP#2.6 ; port PGM
NetP2#2_1: P2#2.1 P4#2.1 U5#2.6(A)
NetP2#2_2: P2#2.2 P4#2.2 U5#2.7(B)
NetP2#2_3: P2#2.3 P4#2.3 U6#2.6(A)
NetP2#2_4: P2#2.4 P4#2.4 U6#2.7(B)
NetP6#3_1: P6#3.1 U4#3.3(IP-) U4#3.4(IP-)
NetP6#3_2: P6#3.2 U4#3.1(IP+) U4#3.2(IP+) ; port INPUT+
NetP_DISP#2_3: P_DISP#2.3 R9#2.3(TAP) ; port Vo
NetP_DISP#2_4: P_DISP#2.4 ; port RS
NetP_DISP#2_6: P_DISP#2.6 ; port DISP_E
NetP_DISP#2_11: P_DISP#2.11 ; port DB0
NetP_DISP#2_12: P_DISP#2.12 ; port DB1
NetP_DISP#2_13: P_DISP#2.13 ; port DB2
NetP_DISP#2_14: P_DISP#2.14 ; port DB3
NetP_DISP#2_15: P_DISP#2.15 R4#2.1
NetQ19#2_3: Q19#2.3(G) R18#2.2 ; port PWR_CTRL
NetR2_MTR_DRV1_Sensor_frontend_2: port EMGCY, sheet MTR_DRV1/EMERGENCY
NetR103_MTR_DRV1_2: port CCW, sheet MTR_DRV1/CCW
NetU4#3_7: U4#3.7(Vout) ; port MEAS_I
NetU5#2_1: U5#2.1(RO) ; port RX
NetU6#2_3: U6#2.3(DE) ; port TX_EN
NetU6#2_4: U6#2.4(DI) ; port TX
NetU7_MTR_DRV1_1: port EN0, sheet MTR_DRV1/SENSE2, sheet MTR_DRV1/EN0
NetU7_MTR_DRV1_3: port EN1, sheet MTR_DRV1/EN1
NetU7_MTR_DRV1_5: port EN2, sheet MTR_DRV1/EN2
NetU7_MTR_DRV1_7: port EN3, sheet MTR_DRV1/EN3
NetU?_MTR_DRV1#2_1: port PS_EN, sheet MTR_DRV1/PS_EN

Not connected (* = marked no-connect by the designer): U3#2 1(SI) 2(SCK) 4(~{CS}) 8(SO); U5#2 4(DI); U6#2 1(RO)

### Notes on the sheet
- (near P6#3) 0 INPUT+
  1 INPUT -
  2 OUTPUT -
  3 OUTPUT +
- Solar Tracking System Controller
- 1
- 1/3
- 2
- Kanawat Senanan

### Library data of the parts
BT1#2 = Battery: Multicell Battery
C1#2 C2#2 C5#3 C12#2 C13#2 C21#2 C28#2 = Cap: Capacitor
C23#2 C24#2 = Cap Semi: Capacitor (Semiconductor SIM Model)
D10#2 = D Zener: Zener Diode
D11#2 D12#2 = Diode 1N4001: 1 Amp General Purpose Rectifier
ICSP#2 P2#2 P4#2 = Header 6: Header, 6-Pin
P3#2 P6#3 = Header 2: Header, 2-Pin
P_DISP#2 = Header 16: Header, 16-Pin
Q19#2 = IRHM9150: Radiation Hardened HEXFET Power MOSFET
R3#2 R4#2 R18#2 R50#2 = Res1: Resistor
R9#2 = Res Tap: Tapped Resistor; pin to pad: 2>3 3>2; Sim Note: Enter the Resistance value and the set point into parameter fields.; Set Position: 0.5
U5#2 U6#2 = MAX485EPA: as U5#1 on sheet main
U18#2 = L78L05ABZ: Positive Voltage Regulator

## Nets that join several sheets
GND: main (35 pins), MTR_DRV1 (9 pins), MTR_DRV1/Sensor frontend (6 pins), current_logger (C5#2.1 U4#2.5), main2 (28 pins), MTR_DRV1 (9 pins), MTR_DRV1/Sensor frontend (6 pins)
HVGND: MTR_DRV1 (13 pins), MTR_DRV1/Sensor frontend (8 pins), MTR_DRV1 (13 pins), MTR_DRV1/Sensor frontend (8 pins)
V5: main (11 pins), MTR_DRV1 (RLY1_MTR_DRV1#1.5 RLY2_MTR_DRV1#1.5 RLY3.5 RLY4.5), MTR_DRV1/Sensor frontend (6 pins), current_logger (U4#2.8), main2 (10 pins), MTR_DRV1 (RLY1_MTR_DRV1#2.5 RLY2_MTR_DRV1#2.5 RLY3_MTR_DRV1.5 RLY4_MTR_DRV1.5), MTR_DRV1/Sensor frontend (6 pins)
V12: MTR_DRV1 (11 pins), MTR_DRV1 (11 pins)
V33: main (5 pins), main2 (C24#2.2 U3#2.3 U3#2.6 U18#2.1)
V36: MTR_DRV1 (12 pins), MTR_DRV1 (12 pins)
VCC: main (13 pins), main2 (9 pins)
NetD1_1: main (P2#1.6 P4#1.6), MTR_DRV1/Sensor frontend (D1.1 R1.2)
NetD1_2: main (P2#1.5 P4#1.5), MTR_DRV1/Sensor frontend (D1.2 U1.1)
NetD1_MTR_DRV1_Sensor_frontend_1: main2 (P2#2.6 P4#2.6), MTR_DRV1/Sensor frontend (D1_MTR_DRV1_Sensor_frontend.1 R1_MTR_DRV1_Sensor_frontend.2)
NetD1_MTR_DRV1_Sensor_frontend_2: main2 (P2#2.5 P4#2.5), MTR_DRV1/Sensor frontend (D1_MTR_DRV1_Sensor_frontend.2 U1_MTR_DRV1_Sensor_frontend.1)
NetR2_2: main (U10.9), MTR_DRV1/Sensor frontend (R2.2 U1.4)
NetR103_2: main (U10.37), MTR_DRV1 (R103.2 R107.2 R111.2 R115.2)
NetR130_MTR_DRV1_Sensor_frontend#1_2: MTR_DRV1 (TRM1.3), MTR_DRV1/Sensor frontend (R130_MTR_DRV1_Sensor_frontend#1.2)
NetR130_MTR_DRV1_Sensor_frontend#2_2: MTR_DRV1 (TRM1_MTR_DRV1.3), MTR_DRV1/Sensor frontend (R130_MTR_DRV1_Sensor_frontend#2.2)
NetR131_MTR_DRV1_Sensor_frontend#1_2: MTR_DRV1 (TRM2.3), MTR_DRV1/Sensor frontend (R131_MTR_DRV1_Sensor_frontend#1.2)
NetR131_MTR_DRV1_Sensor_frontend#2_2: MTR_DRV1 (TRM2_MTR_DRV1.3), MTR_DRV1/Sensor frontend (R131_MTR_DRV1_Sensor_frontend#2.2)
NetR132_MTR_DRV1_Sensor_frontend#1_2: MTR_DRV1 (TRM3.3), MTR_DRV1/Sensor frontend (R132_MTR_DRV1_Sensor_frontend#1.2)
NetR132_MTR_DRV1_Sensor_frontend#2_2: MTR_DRV1 (TRM3_MTR_DRV1.3), MTR_DRV1/Sensor frontend (R132_MTR_DRV1_Sensor_frontend#2.2)
NetR133_MTR_DRV1_Sensor_frontend#1_2: MTR_DRV1 (TRM4.3), MTR_DRV1/Sensor frontend (R133_MTR_DRV1_Sensor_frontend#1.2)
NetR133_MTR_DRV1_Sensor_frontend#2_2: MTR_DRV1 (TRM4_MTR_DRV1.3), MTR_DRV1/Sensor frontend (R133_MTR_DRV1_Sensor_frontend#2.2)
NetU7_1: main (U10.33), MTR_DRV1 (U7.1)
NetU7_3: main (U10.34), MTR_DRV1 (U7.3)
NetU7_5: main (U10.35), MTR_DRV1 (U7.5)
NetU7_7: main (U10.36), MTR_DRV1 (U7.7)
NetU7_MTR_DRV1_1: MTR_DRV1 (U7_MTR_DRV1.1), MTR_DRV1/Sensor frontend (U8_MTR_DRV1_Sensor_frontend.6)
NetU8_2: main (U10.3), MTR_DRV1/Sensor frontend (U8.2)
NetU8_4: main (U10.4), MTR_DRV1/Sensor frontend (U8.4)
NetU8_6: main (U10.5), MTR_DRV1/Sensor frontend (U8.6)
NetU8_8: main (U10.6), MTR_DRV1/Sensor frontend (U8.8)
NetU10_27: main (U10.27), MTR_DRV1 (U?_MTR_DRV1#1.1)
